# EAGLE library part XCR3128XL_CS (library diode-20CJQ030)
Xilinx's XCR3128XL 128 Macrocell CPLD Features: Low power 3.3V 128 macrocell CPLD 6.0 ns pin-to-pin logic delays System frequencies up to 175 MHz 128 macrocells with 3,000 usable gates Available in small footprint packages -144-pin TQFP (108 user I/O pins) - 144-ball CS BGA (108 user I/O) - 100-pin VQFP (84 user I/O) Optimized for 3.3V systems - Ultra low power operation - 5V tolerant I/O pins with 3.3V core supply - Advanced 0.35 micron five layer metal EEPROM process - Fast Zero Power? (FZP) CMOS design technology - 3.3V PCI electrical specification compatible outputs (no internal clamp diode on any input or I/O) Advanced system features - In-system programming - Input registers - Predictable timing model - Up to 23 available clocks per function block - Excellent pin retention during design changes - Full IEEE Standard 1149.1 boundary-scan (JTAG) - Four global clocks - Eight product term control terms per function block Fast ISP programming times Port Enable pin for additional I/O 2.7V to 3.6V supply voltage at industrial temperature range Programmable slew rate control per output Security bit prevents unauthorized access Refer to XPLA3 family data sheet (DS012) for architecture description Description: The XCR3128XL is a 3.3V 128 macrocell CPLD targeted at power sensitive designs that require leading edge programmable logic solutions. A total of eight function blocks provide 3,000 usable gates. Pin-to-pin propagation delays are 6.0 ns with a maximum system frequency of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
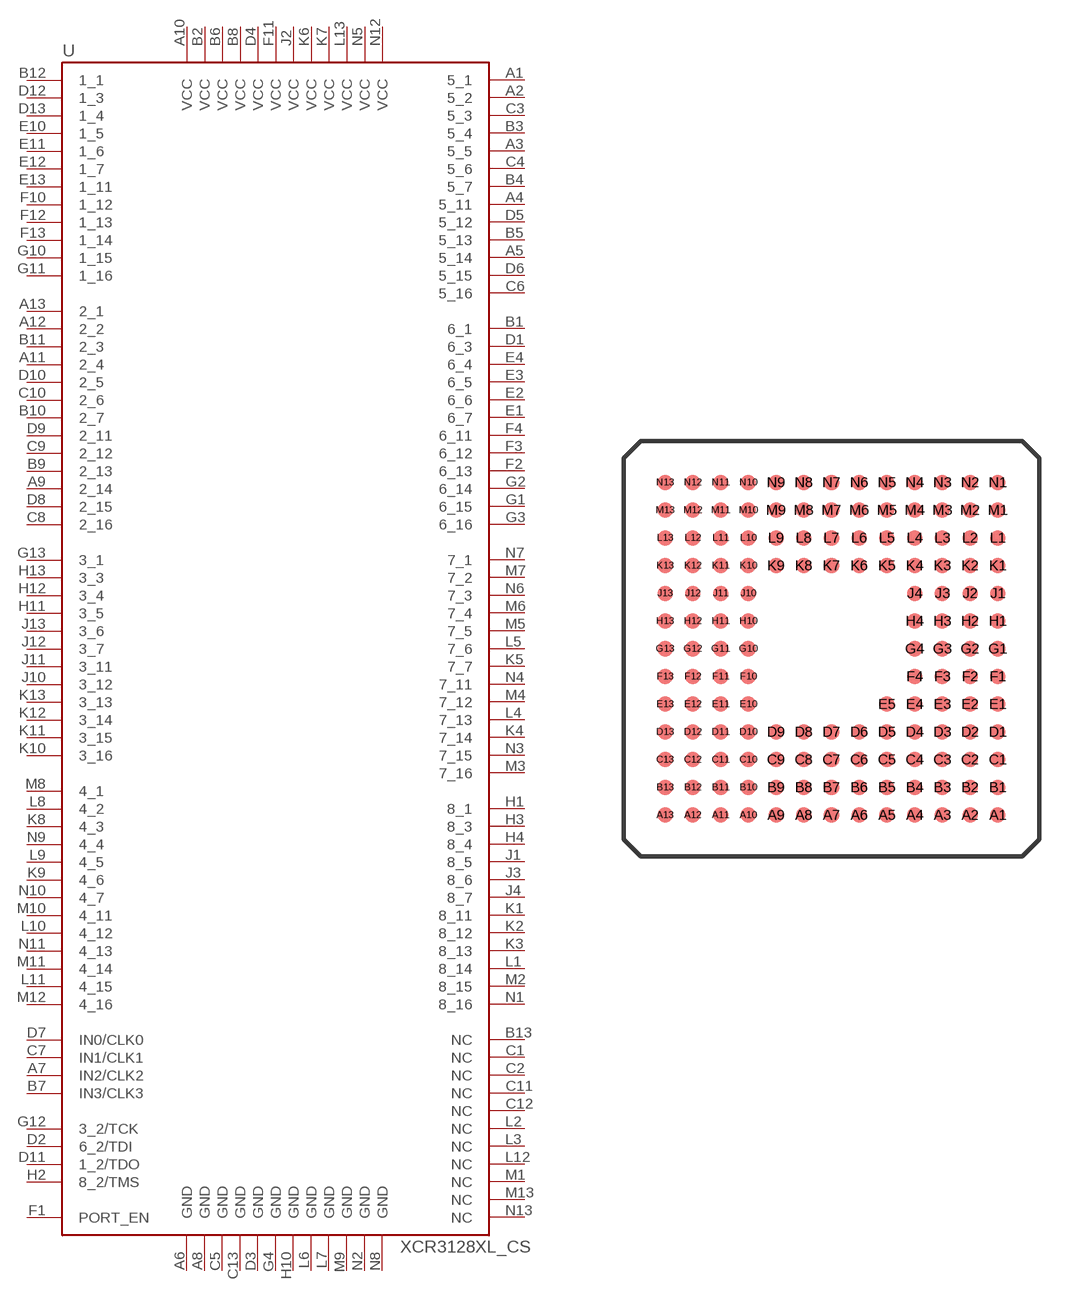
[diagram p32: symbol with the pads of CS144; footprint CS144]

Designator prefix U

## XCR3128XL_CS  [CS144]
A1  5_1
A2  5_2
A3  5_5
A4  5_11
A5  5_14
A6  GND  pwr
A7  IN2/CLK2
A8  GND  pwr
A9  2_14
A10  VCC  pwr
A11  2_4
A12  2_2
A13  2_1
B1  6_1
B2  VCC  pwr
B3  5_4
B4  5_7
B5  5_13
B6  VCC  pwr
B7  IN3/CLK3
B8  VCC  pwr
B9  2_13
B10  2_7
B11  2_3
B12  1_1
B13  NC  nc
C1  NC  nc
C2  NC  nc
C3  5_3
C4  5_6
C5  GND  pwr
C6  5_16
C7  IN1/CLK1
C8  2_16
C9  2_12
C10  2_6
C11  NC  nc
C12  NC  nc
C13  GND  pwr
D1  6_3
D2  6_2/TDI
D3  GND  pwr
D4  VCC  pwr
D5  5_12
D6  5_15
D7  IN0/CLK0
D8  2_15
D9  2_11
D10  2_5
D11  1_2/TDO
D12  1_3
D13  1_4
E1  6_7
E2  6_6
E3  6_5
E4  6_4
E10  1_5
E11  1_6
E12  1_7
E13  1_11
F1  PORT_EN  in
F2  6_13
F3  6_12
F4  6_11
F10  1_12
F11  VCC  pwr
F12  1_13
F13  1_14
G1  6_15
G2  6_14
G3  6_16
G4  GND  pwr
G10  1_15
G11  1_16
G12  3_2/TCK
G13  3_1
H1  8_1
H2  8_2/TMS
H3  8_3
H4  8_4
H10  GND  pwr
H11  3_5
H12  3_4
H13  3_3
J1  8_5
J2  VCC  pwr
J3  8_6
J4  8_7
J10  3_12
J11  3_11
J12  3_7
J13  3_6
K1  8_11
K2  8_12
K3  8_13
K4  7_14
K5  7_7
K6  VCC  pwr
K7  VCC  pwr
K8  4_3
K9  4_6
K10  3_16
K11  3_15
K12  3_14
K13  3_13
L1  8_14
L2  NC  nc
L3  NC  nc
L4  7_13
L5  7_6
L6  GND  pwr
L7  GND  pwr
L8  4_2
L9  4_5
L10  4_12
L11  4_15
L12  NC  nc
L13  VCC  pwr
M1  NC  nc
M2  8_15
M3  7_16
M4  7_12
M5  7_5
M6  7_4
M7  7_2
M8  4_1
M9  GND  pwr
M10  4_11
M11  4_14
M12  4_16
M13  NC  nc
N1  8_16
N2  GND  pwr
N3  7_15
N4  7_11
N5  VCC  pwr
N6  7_3
N7  7_1
N8  GND  pwr
N9  4_4
N10  4_7
N11  4_13
N12  VCC  pwr
N13  NC  nc

## Footprint CS144 (pad centres in mm)
Chip Scale BGA (CS144/CSG144) Package - 144-ball CS BGA (108 user I/O) - Pad diameter: 0.45 mm - Pitch: 0.8mm Please send any comments to: messi@users.sourceforge.net
smd 0.45 x 0.45: A1 4.8,-4.8; A2 4,-4.8; A3 3.2,-4.8; A4 2.4,-4.8; A5 1.6,-4.8; A6 0.8,-4.8; A7 0,-4.8; A8 -0.8,-4.8; A9 -1.6,-4.8; A10 -2.4,-4.8; A11 -3.2,-4.8; A12 -4,-4.8; A13 -4.8,-4.8; B1 4.8,-4; B2 4,-4; B3 3.2,-4; B4 2.4,-4; B5 1.6,-4; B6 0.8,-4; B7 0,-4; B8 -0.8,-4; B9 -1.6,-4; B10 -2.4,-4; B11 -3.2,-4; B12 -4,-4; B13 -4.8,-4; C1 4.8,-3.2; C2 4,-3.2; C3 3.2,-3.2; C4 2.4,-3.2; C5 1.6,-3.2; C6 0.8,-3.2; C7 0,-3.2; C8 -0.8,-3.2; C9 -1.6,-3.2; C10 -2.4,-3.2; C11 -3.2,-3.2; C12 -4,-3.2; C13 -4.8,-3.2; D1 4.8,-2.4; D2 4,-2.4; D3 3.2,-2.4; D4 2.4,-2.4; D5 1.6,-2.4; D6 0.8,-2.4; D7 0,-2.4; D8 -0.8,-2.4; D9 -1.6,-2.4; D10 -2.4,-2.4; D11 -3.2,-2.4; D12 -4,-2.4; D13 -4.8,-2.4; E1 4.8,-1.6; E2 4,-1.6; E3 3.2,-1.6; E4 2.4,-1.6; E5 1.6,-1.6; E10 -2.4,-1.6; E11 -3.2,-1.6; E12 -4,-1.6; E13 -4.8,-1.6; F1 4.8,-0.8; F2 4,-0.8; F3 3.2,-0.8; F4 2.4,-0.8; F10 -2.4,-0.8; F11 -3.2,-0.8; F12 -4,-0.8; F13 -4.8,-0.8; G1 4.8,0; G2 4,0; G3 3.2,0; G4 2.4,0; G10 -2.4,0; G11 -3.2,0; G12 -4,0; G13 -4.8,0; H1 4.8,0.8; H2 4,0.8; H3 3.2,0.8; H4 2.4,0.8; H10 -2.4,0.8; H11 -3.2,0.8; H12 -4,0.8; H13 -4.8,0.8; J1 4.8,1.6; J2 4,1.6; J3 3.2,1.6; J4 2.4,1.6; J10 -2.4,1.6; J11 -3.2,1.6; J12 -4,1.6; J13 -4.8,1.6; K1 4.8,2.4; K2 4,2.4; K3 3.2,2.4; K4 2.4,2.4; K5 1.6,2.4; K6 0.8,2.4; K7 0,2.4; K8 -0.8,2.4; K9 -1.6,2.4; K10 -2.4,2.4; K11 -3.2,2.4; K12 -4,2.4; K13 -4.8,2.4; L1 4.8,3.2; L2 4,3.2; L3 3.2,3.2; L4 2.4,3.2; L5 1.6,3.2; L6 0.8,3.2; L7 0,3.2; L8 -0.8,3.2; L9 -1.6,3.2; L10 -2.4,3.2; L11 -3.2,3.2; L12 -4,3.2; L13 -4.8,3.2; M1 4.8,4; M2 4,4; M3 3.2,4; M4 2.4,4; M5 1.6,4; M6 0.8,4; M7 0,4; M8 -0.8,4; M9 -1.6,4; M10 -2.4,4; M11 -3.2,4; M12 -4,4; M13 -4.8,4; N1 4.8,4.8; N2 4,4.8; N3 3.2,4.8; N4 2.4,4.8; N5 1.6,4.8; N6 0.8,4.8; N7 0,4.8; N8 -0.8,4.8; N9 -1.6,4.8; N10 -2.4,4.8; N11 -3.2,4.8; N12 -4,4.8; N13 -4.8,4.8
